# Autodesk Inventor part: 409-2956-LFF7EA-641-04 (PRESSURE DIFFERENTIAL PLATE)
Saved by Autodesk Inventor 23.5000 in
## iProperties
Created: 2010-06
Part Number: 409-2956-LFF7EA-641-04 (PRESSURE DIFFERENTIAL PLATE)
Cost Center: 0 lbmass
Material: A1011 HR STEEL
Document SubType Name: Sheet Metal
Designer: S. Boerckel
Authority: 0 in^3
Mass: 8532.6 g
Surface Area: 6483.36 cm^2
Volume: 1085.57 cm^3
Density: 7.86 g/cm^3
Sheet Metal Rule: 10GA
Description: PRESSUER DIFFERNTIAL PLATE
Flat Pattern Width: 59.69 cm
Flat Pattern Length: 59.69 cm
Flat Pattern Area: 3562.9 cm^2
Sheet Metal Width: 23.5000 in
Sheet Metal Length: 552.2500 in^2
User Status: SHEAR
SaveDate: 2008-01-15
SaveTime: 10:24
FileName: Sheet Metal
Wide: =<Flat Pattern Width>cm
Length: =<Flat Pattern Length>cm
Thickness: 0.1345 in
SMR: =<Sheet Metal Rule> - <Material>
Author: S. Boerckel
Revision Number: B
Subject: DEMIN WATER FORWARDING PUMP SKID-7EA
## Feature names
1. Hole1
2. Hole2
3. Hole3
4. Hole4
5. Rectangular Pattern1
6. Plate1
